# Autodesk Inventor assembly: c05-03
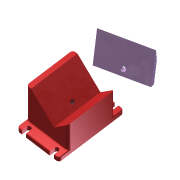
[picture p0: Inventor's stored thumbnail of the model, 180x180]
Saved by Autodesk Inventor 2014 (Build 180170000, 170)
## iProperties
Created: 2010-11
Part Number: c05-03
Document SubType Name: Assembly
Designer: Thom Tremblay
Author: Thom Tremblay
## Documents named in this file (3)
- C:\Inventor 2014 Essentials\Assemblies\Chapter 05\c05-03.iam
- C:\Inventor 2014 Essentials\Parts\Chapter 05\c05-03.ipt
- C:\Inventor 2014 Essentials\Parts\Chapter 05\c05-04.ipt
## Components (2 placed, 2 different names)
1. c05-03:1
2. c05-04:1
